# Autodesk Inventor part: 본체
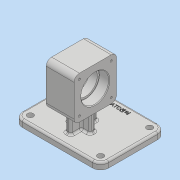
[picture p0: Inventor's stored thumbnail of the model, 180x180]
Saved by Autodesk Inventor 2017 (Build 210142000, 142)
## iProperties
Part Number: 본체
Material: 일반
Document SubType Name: Modeling
Designer: mrc
Density: 1 g/cm^3
Appearance: 기본값
Mass: 253.042 g
Surface Area: 542.794 cm^2
Volume: 253.042 cm^3
Author: mrc
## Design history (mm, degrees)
sketch "스케치1"
  geometry: L1 (-65, -49)-(65, -49); L2 (65, -49)-(65, 49); L3 (65, 49)-(-65, 49); L4 (-65, 49)-(-65, -49); L5 (-65, -49)-(65, 49); L6 (65, -49)-(-65, 49); 1 further point
  constraints: 12 end point, 2 midpoint, 2 parallel, 1 horizontal, 1 perpendicular
  dimensions: "d0" = 130 distance of L2.end L3.end; "d1" = 98 distance of L1.end L2.end
extrude "돌출1" new body sketch "스케치1" distance "d2" = 10; taper "d3" = 0 deg
node "작업 평면1"
sketch "스케치2"
  geometry: L1 (-21, 19)-(21, 19); L2 (21, 19)-(21, -45); L3 (21, -45)-(-21, -45); L4 (-21, -45)-(-21, 19); L5 (-21, 19)-(21, -45); L6 (21, 19)-(-21, -45); L7 (65, -49)-(65, 49) reference; L8 (65, 49)-(-65, 49) reference; 2 further points
  constraints: 12 end point, 2 midpoint, 2 parallel, 1 horizontal, 1 perpendicular
  dimensions: "d5" = 42 distance of L1.start L1.end; "d6" = 64 distance of L1.end L2.end; "d7" = 65 distance from line of L7 point (0, -13); "d8" = 62 distance from line of L8 point (0, -13)
extrude "돌출2" join sketch "스케치2" distance "d9" = 64; taper "d10" = 0 deg
sketch "스케치3"
  geometry: L1 (-17, -9)-(17, -9); L2 (17, -9)-(17, -17); L3 (17, -17)-(-17, -17); L4 (-17, -17)-(-17, -9); L5 (-17, -9)-(17, -17); L6 (17, -9)-(-17, -17); L7 (65, -49)-(65, 49) reference; L8 (65, 49)-(-65, 49) reference; L9 (-4, 7)-(4, 7); L10 (4, 7)-(4, -33); L11 (4, -33)-(-4, -33); L12 (-4, -33)-(-4, 7); L13 (-4, 7)-(4, -33); L14 (4, 7)-(-4, -33); 3 further points
  constraints: 24 end point, 4 midpoint, 4 parallel, 2 horizontal, 2 perpendicular
  dimensions: "d11" = 34 distance of L2.end L3.end; "d12" = 8 distance of L3.end L1.start; "d13" = 65 distance from line of L7 point (0, -13); "d14" = 62 distance from line of L8 point (0, -13); "d15" = 40 distance of L9.end L10.end; "d16" = 8 distance of L10.end L11.end; "d17" = 65 distance from line of L7 point (0, -13); "d18" = 62 distance from line of L8 point (0, -13)
extrude "돌출3" join sketch "스케치3" stored distance "d19" = 64; taper "d20" = 0 deg
sketch "스케치4"
  geometry: L1 (64, 64)-(64, 0) reference; L2 (0, 64)-(0, 0) reference; C1 r 21 at (32, 32); 2 further points
  constraints: 1 centre point, 1 horizontal alignment, 1 midpoint
  dimensions: "d21" = 42 diameter of C1; "d22" = 32 distance from line of L2 C1.centre
extrude "돌출4" cut sketch "스케치4" distance "d23" = 15; taper "d24" = 0 deg
sketch "스케치5"
  geometry: C1 r 18 at (0, 0); C2 r 21 at (0, 0) reference; 1 further point
  constraints: 1 centre point, 1 concentric
  dimensions: "d25" = 36 diameter of C1
extrude "돌출5" cut sketch "스케치5" distance "d26" = 12; taper "d27" = 0 deg
sketch "스케치6"
  geometry: C1 r 21 at (-32, 32); C2 r 21 at (-32, 32) reference; 1 further point
  constraints: 1 centre point, 1 concentric
  dimensions: "d28" = 42 diameter of C1
extrude "돌출6" cut sketch "스케치6" distance "d29" = 15; taper "d30" = 0 deg
sketch "스케치9"
  geometry: L1 (-65, 49)-(-65, -49) reference; L2 (65, 49)-(-65, 49) reference; L3 (-65, -49)-(65, -49) reference; L4 (65, -49)-(65, 49) reference; C1 r 4.5 at (-53, 37); C2 r 4.5 at (-53, -37); C3 r 4.5 at (53, -37); C4 r 4.5 at (53, 37); 1 further point
  constraints: 4 centre point
  dimensions: "d42" = 9 diameter of C1; "d43" = 9 diameter of C2; "d44" = 9 diameter of C3; "d45" = 9 diameter of C4; "d46" = 12 distance from line of C1.centre L1; "d47" = 12 distance from line of L2 C1.centre; "d48" = 12 distance from line of L3 C2.centre; "d49" = 12 distance from line of L1 C2.centre; "d50" = 12 distance from line of C3.centre L3; "d51" = 12 distance from line of C3.centre L4; "d52" = 12 distance from line of L4 C4.centre; "d53" = 12 distance from line of C4.centre L2
extrude "돌출7" cut sketch "스케치9" distance "d54" = 10; taper "d55" = 0 deg
sketch "스케치10"
  geometry: L1 (0, 0)-(0, 64) reference; L2 (0, 64)-(-64, 64) reference; 2 further points
  dimensions: "d56" = 8 distance from line of L1 point (-8, 56); "d57" = 8 distance from line of point (-8, 56) L2
hole "구멍1" sketch "스케치10" at (-8, 56) diameter "d58" = 3.242; stored, may be unused: countersink angle "d62" = 90 deg, drill point angle "d64" = 118 deg; dims "d59" = 8, "d60" = 4, "d61" = 2, "d63" = 10
sketch "스케치11"
  geometry: L1 (0, 0)-(-64, 0) reference; L2 (0, 0)-(0, 64) reference; L3 (-64, 0)-(-64, 64) reference; L4 (0, 64)-(-64, 64) reference; 4 further points
  dimensions: "d65" = 8 distance from line of L1 point (-8, 8); "d66" = 8 distance from line of L2 point (-8, 8); "d67" = 8 distance from line of L3 point (-56, 8); "d68" = 8 distance from line of L1 point (-56, 8); "d69" = 8 distance from line of L3 point (-56, 56); "d70" = 8 distance from line of L4 point (-56, 56)
hole "구멍2" sketch "스케치11" at (-56, 56), (-56, 8), (-8, 8) diameter "d71" = 3.242; stored, may be unused: countersink angle "d75" = 90 deg, drill point angle "d77" = 118 deg; dims "d72" = 8, "d73" = 4, "d74" = 2, "d76" = 10
node "작업 평면2"
sketch "스케치12"
  geometry: L1 (65, 49)-(-65, 49) reference; 3 further points
  constraints: 1 midpoint, 1 vertical alignment, 1 other
  dimensions: "d79" = 10 distance from line of point (0, 39) L1
feature "엠보싱1" sketch "스케치12" dims "d0" = 130, "d1" = 98, "d80" = 0.5, "d81" = 0
fillet "모깎기1" dims "d82" = 8
fillet "모깎기2" dims "d83" = 12
fillet "모깎기3" dims "d84" = 3
chamfer "모따기1" distance "d85" = 1; stored, may be unused: second distance "d86" = 2, angle "d87" = 45 deg
chamfer "모따기2" distance "d88" = 1; stored, may be unused: second distance "d89" = 2, angle "d90" = 45 deg
fillet "모깎기4" dims "d91" = 3
fillet "모깎기5" dims "d92" = 3
fillet "모깎기6" dims "d93" = 3
fillet "모깎기7" dims "d94" = 0.3
node "솔리드1"
mirror "미러1"
other parameters: "d4" = 92, "d78" = 0
